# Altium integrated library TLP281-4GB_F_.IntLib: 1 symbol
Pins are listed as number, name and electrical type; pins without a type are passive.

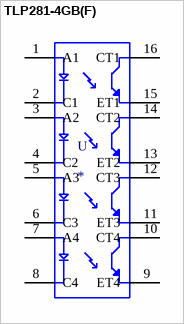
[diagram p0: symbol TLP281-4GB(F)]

## TLP281-4GB(F)
designator U
Optocoupler DC-IN 4-CH Transistor DC-OUT 16-Pin SOP; MP: TLP281-4GB_F_; MF: Toshiba
footprint SOIC127P700X210-16N
pins: 1 A1, 2 C1, 3 A2, 4 C2, 5 A3, 6 C3, 7 A4, 8 C4, 9 ET4, 10 CT4, 11 ET3, 12 CT3, 13 ET2, 14 CT2, 15 ET1, 16 CT1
